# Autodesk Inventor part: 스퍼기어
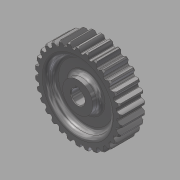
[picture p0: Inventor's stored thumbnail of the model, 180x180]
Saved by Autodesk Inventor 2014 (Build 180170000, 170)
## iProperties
Created: 2015-11
Part Number: 스퍼기어
Material: 강철, 탄소
Document SubType Name: Modeling
Designer: mduedu
Density: 1 g/cm^3
Appearance: 반광택
Author: mduedu
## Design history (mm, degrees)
sketch "스케치1"
  geometry: C1 r 28.75 at (0, 0); 1 further point
  constraints: 1 centre point, 1 coincident
  dimensions: "d0" = 57.5 diameter of C1
extrude "돌출1" new body sketch "스케치1" stored distance "d2" = 18; taper "d3" = 0 deg
sketch "스케치2" dims "d4" = 60
  geometry: L1 (0, 0)-(0, 32); L2 (-32, 0)-(32, 0); L3 (-2.07, 0)-(-2.07, 40.614); L4 (-2.07, 40.614)-(-1.57, 40.614); L5 (-1.57, 40.614)-(-1.57, 0); L6 (-0.57, 0)-(-0.57, 40.614); L7 (-0.57, 40.614)-(0, 40.614); L8 (0, 40.614)-(0, 0); A1 r 32 centre (0, 0) between (0.57, 31.995) and (-0.57, 31.995); A2 r 21.436 centre (18.143, 21.54) between (-0.57, 31.995) and (-2.07, 28.675); A3 r 21.436 centre (-18.143, 21.54) between (2.07, 28.675) and (0.57, 31.995); A4 r 32 centre (0, 0) between (32, 0) and (0.57, 31.995); A5 r 32 centre (0, 0) between (-0.57, 31.995) and (32, 0); A6 r 28.75 centre (0, 0) between (2.07, 28.675) and (-2.07, 28.675); 4 further points
  constraints: 17 point on circle, 16 end point, 6 centre point, 6 point on line, 5 perpendicular, 4 coincident, 3 symmetric about line, 2 collinear, 1 midpoint, 1 parallel, 1 vertical, 6 other
  dimensions: "d6" = 64 diameter of A1; "d7" = 0.5 distance between parallel lines of L5 L3; "d8" = 1 distance between parallel lines of L6 L5; "d9" = 40.61409 distance of L4.end L5.end; "d10" = 1.57 distance between parallel lines of L8 L5
extrude "돌출2" join sketch "스케치2" stored distance "d11" = 18; taper "d12" = 0 deg
fillet "모깎기1" dims "d16" = 0.5
chamfer "모따기3" distance "d26" = 1; stored, may be unused: second distance "d27" = 2, angle "d28" = 45 deg
sketch "스케치3"
  geometry: C1 r 23 at (0, 0); C2 r 11 at (0, 0); 1 further point
  constraints: 2 centre point, 2 coincident
  dimensions: "d32" = 46 diameter of C1; "d33" = 22 diameter of C2
extrude "돌출3" cut sketch "스케치3" distance "d34" = 6; taper "d35" = 0 deg
fillet "모깎기2" dims "d36" = 3
hole "구멍1" diameter "d39" = 10; stored, may be unused: countersink angle "d43" = 90 deg, drill point angle "d45" = 118 deg; dims "d37" = 10, "d38" = 10, "d40" = 6, "d41" = 4, "d42" = 2, "d44" = 8
sketch "스케치5"
  geometry: L1 (-1.5, 0)-(1.5, 0); L2 (1.5, 0)-(1.5, 6.4); L3 (1.5, 6.4)-(-1.5, 6.4); L4 (-1.5, 6.4)-(-1.5, 0); 2 further points
  constraints: 8 end point, 2 parallel, 1 coincident, 1 horizontal, 1 midpoint, 1 perpendicular
  dimensions: "d46" = 3 distance of L2.end L3.end; "d48" = 6.4 distance of L1.end L2.end
extrude "돌출4" cut sketch "스케치5" stored distance "d49" = 6; taper "d50" = 0 deg
chamfer "모따기4" distance "d51" = 0.5; stored, may be unused: second distance "d52" = 2, angle "d53" = 45 deg
node "솔리드1"
pattern_circular "원형 패턴3" dims "d30" = 360 deg
mirror "대칭1"
